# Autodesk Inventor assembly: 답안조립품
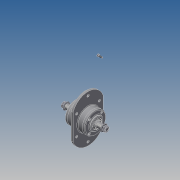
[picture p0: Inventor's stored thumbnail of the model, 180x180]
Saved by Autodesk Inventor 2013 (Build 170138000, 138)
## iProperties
Created: 2015-02
Part Number: 답안조립품
Document SubType Name: Assembly
Designer: kb146
Author: kb146
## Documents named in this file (12)
- C:\Users\kb146\Desktop\450207V1024\답안조립품.iam
- C:\Users\kb146\Desktop\450207V1024\1-본체.ipt
- C:\Users\kb146\Desktop\450207V1024\2-커버.ipt
- C:\Users\kb146\Desktop\450207V1024\3-축.ipt
- C:\Users\kb146\Desktop\450207V1024\4-V벨트풀리.ipt
- C:\Users\kb146\Desktop\450207V1024\5-체인 스프로킷.ipt
- C:\Users\kb146\Desktop\450207V1024\6-베어링 6206.ipt
- C:\Users\kb146\Desktop\450207V1024\7-부시.ipt
- C:\Users\kb146\Desktop\450207V1024\8-오일실 30x42.ipt
- C:\Users\kb146\Desktop\450207V1024\9-M16-너트.ipt
- C:\Users\kb146\Desktop\450207V1024\10-M6.ipt
- C:\Users\kb146\Desktop\450207V1024\11-키 6x6.ipt
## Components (16 placed, 11 different names)
1. 1-본체:1
2. 2-커버:1
3. 3-축:1
4. 4-V벨트풀리:1
5. 5-체인 스프로킷:1
6. 6-베어링 6206:1
7. 7-부시:1
8. 8-8-오일실 30x42:1
9. 9-M16 너트:1
10. 10-M6:1
11. 11-키 6x6:1
12. 11-키 6x6:2
13. 2-커버:2
14. 8-8-오일실 30x42:2
15. 6-베어링 6206:2
16. 9-M16 너트:2
